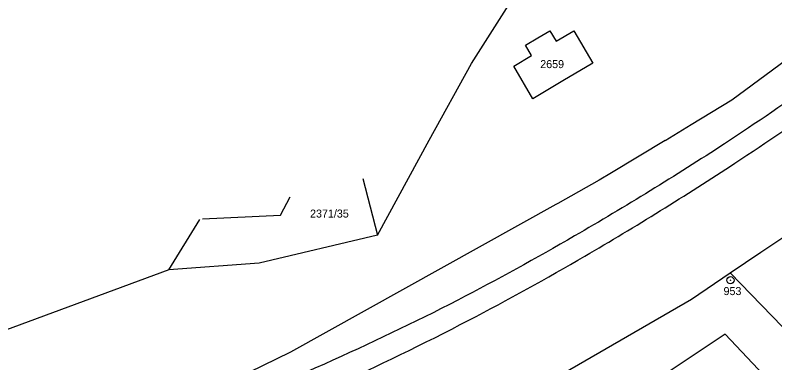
# Model space of a CAD drawing. Extents: x -825057 to -819383, y -1071633 to -1067888.
# Drawn here: x -820228.7 to -820067.4, y -1069506.6 to -1069432.8 of the extents above; entities that cross this region are included whole.
import ezdxf

# ---------------------------------------------------------------- set-up
doc = ezdxf.new("R2010")
doc.units = 0
for name, color, linetype in [('Vrstva 1', 7, 'Continuous'), ('Vrstva 10', 7, 'Continuous'), ('Vrstva 17', 7, 'Continuous'), ('Vrstva 18', 7, 'Continuous'), ('Vrstva 19', 7, 'Continuous'), ('Vrstva 24', 7, 'Continuous'), ('Vrstva 4', 7, 'Continuous')]:
    doc.layers.add(name, color=color, linetype=linetype)

msp = doc.modelspace()

# ---------------------------------------------------------------- linework, layer by layer
at = {"layer": 'Vrstva 1'}
for p, q in [((-820131.78, -1069443.08), (-820116.82, -1069419.54)), ((-820117.71, -1069437.67), (-820115.12, -1069436.17)), ((-820115.12, -1069436.17), (-820113.84, -1069438.36)), ((-820113.84, -1069438.36), (-820110.04, -1069436.13)), ((-820110.04, -1069436.13), (-820106.02, -1069443)), ((-820120.31, -1069439.2), (-820117.71, -1069437.67)), ((-820119.02, -1069441.4), (-820120.31, -1069439.2)), ((-820122.81, -1069443.63), (-820119.02, -1069441.4)), ((-820140.76, -1069459.33), (-820131.78, -1069443.08)), ((-820106.02, -1069443), (-820112.4, -1069446.78)), ((-820118.76, -1069450.55), (-820122.81, -1069443.63)), ((-820112.4, -1069446.78), (-820118.76, -1069450.55)), ((-820151.73, -1069479.47), (-820140.76, -1069459.33)), ((-820070.35, -1069483.1), (-820044.32, -1069465.59)), ((-820154.86, -1069467.45), (-820151.73, -1069479.47)), ((-820172.35, -1069475.24), (-820170.27, -1069471.33)), ((-820188.93, -1069476.03), (-820172.35, -1069475.24)), ((-820196.03, -1069486.83), (-820189.48, -1069476.17)), ((-820151.73, -1069479.47), (-820176.84, -1069485.41)), ((-820076.89, -1069487.51), (-820070.35, -1069483.1)), ((-820176.84, -1069485.41), (-820196.03, -1069486.83)), ((-820196.03, -1069486.83), (-820236.1, -1069501.64)), ((-820085.07, -1069493.07), (-820076.89, -1069487.51)), ((-820076.89, -1069487.51), (-820060.65, -1069504.23)), ((-820112.25, -1069508.76), (-820085.07, -1069493.07)), ((-820077.91, -1069500.52), (-820093.39, -1069510.76)), ((-820077.91, -1069500.52), (-820067.83, -1069511.15))]:
    msp.add_line(p, q, dxfattribs=at)
at = {"layer": 'Vrstva 10'}
for points in [[(-819936.83, -1069349.47), (-819975.71, -1069383.16), (-819999.35, -1069402.16), (-820038.47, -1069432.26), (-820078.04, -1069460.09), (-820109.89, -1069479.65), (-820134.7, -1069493.27), (-820163.02, -1069506.83), (-820195.64, -1069520.53), (-820237.28, -1069534.88), (-820272.75, -1069545.33)], [(-820271.07, -1069550.51), (-820235.31, -1069539.9), (-820193.69, -1069525.37), (-820161.56, -1069511.74), (-820132.38, -1069497.54), (-820107.7, -1069483.92), (-820075.84, -1069464.22), (-820035.7, -1069436.13), (-819996.53, -1069406.13), (-819972.84, -1069386.82), (-819933.47, -1069352.83)]]:
    msp.add_spline(points, degree=3, dxfattribs=at)
at = {"layer": 'Vrstva 24'}
for radius in [0.75, 0.0327]:
    msp.add_circle((-820076.79, -1069489.04), radius, dxfattribs=at)
at = {"layer": 'Vrstva 4'}
for p, q in [((-820076.53, -1069450.8), (-820004.18, -1069397.53)), ((-820085.17, -1069456.04), (-820076.53, -1069450.8)), ((-820090.69, -1069459.39), (-820085.17, -1069456.04)), ((-820090.69, -1069459.39), (-820102.04, -1069466.27)), ((-820102.04, -1069466.27), (-820104.67, -1069467.86)), ((-820104.67, -1069467.86), (-820113.47, -1069472.75)), ((-820113.85, -1069472.96), (-820170.24, -1069504.29)), ((-820113.47, -1069472.75), (-820113.85, -1069472.96)), ((-820170.24, -1069504.29), (-820179.08, -1069508.65))]:
    msp.add_line(p, q, dxfattribs=at)

# ---------------------------------------------------------------- texts
at = {"layer": 'Vrstva 17'}
msp.add_text('953', height=1.7, dxfattribs=at).set_placement((-820078.27, -1069492.2))
at = {"layer": 'Vrstva 18'}
msp.add_text('2371/35', height=1.7, dxfattribs=at).set_placement((-820166.063, -1069475.76))
at = {"layer": 'Vrstva 19'}
msp.add_text('2659', height=1.7, dxfattribs=at).set_placement((-820117.188, -1069444.06))

doc.saveas('drawing.dxf')
